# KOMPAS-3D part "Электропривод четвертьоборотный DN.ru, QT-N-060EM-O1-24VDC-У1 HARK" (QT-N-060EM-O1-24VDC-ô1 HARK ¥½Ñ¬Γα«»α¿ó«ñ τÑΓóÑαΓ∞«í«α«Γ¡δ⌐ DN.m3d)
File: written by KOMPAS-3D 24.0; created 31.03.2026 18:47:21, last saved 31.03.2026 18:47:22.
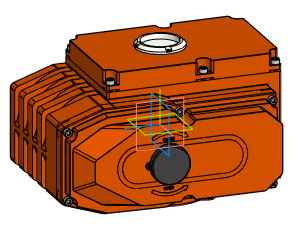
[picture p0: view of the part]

Document properties: Автор: DN.RU; Полное имя файла: D:\PROJECT CAD\DN.RU\...195\Исходники\24В\QT-N-060EM-O1-24VDC-У1 HARK Электропривод четвертьоборотный DN.ru\QT-N-060EM-O1-24VDC-У1 HARK Электропривод четвертьоборотный DN.m3d

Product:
- Body: Твердое тело1  | qty 1
    Масса: 37.407802
- Part/product: Электропривод четвертьоборотный DN.ru  | designation QT-N-060EM-O1-24VDC-У1 HARK
    Масса: 9.3
    Раздел спецификации: Прочие изделия
    Комментарий: D300-05875
    Примечание: D300-16806
    additional columns: Сталь

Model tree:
1. Твердое тело1  (labels: Твердое тело1)

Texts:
  QT-N-060EM-O1-24VDC-У1 HARK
